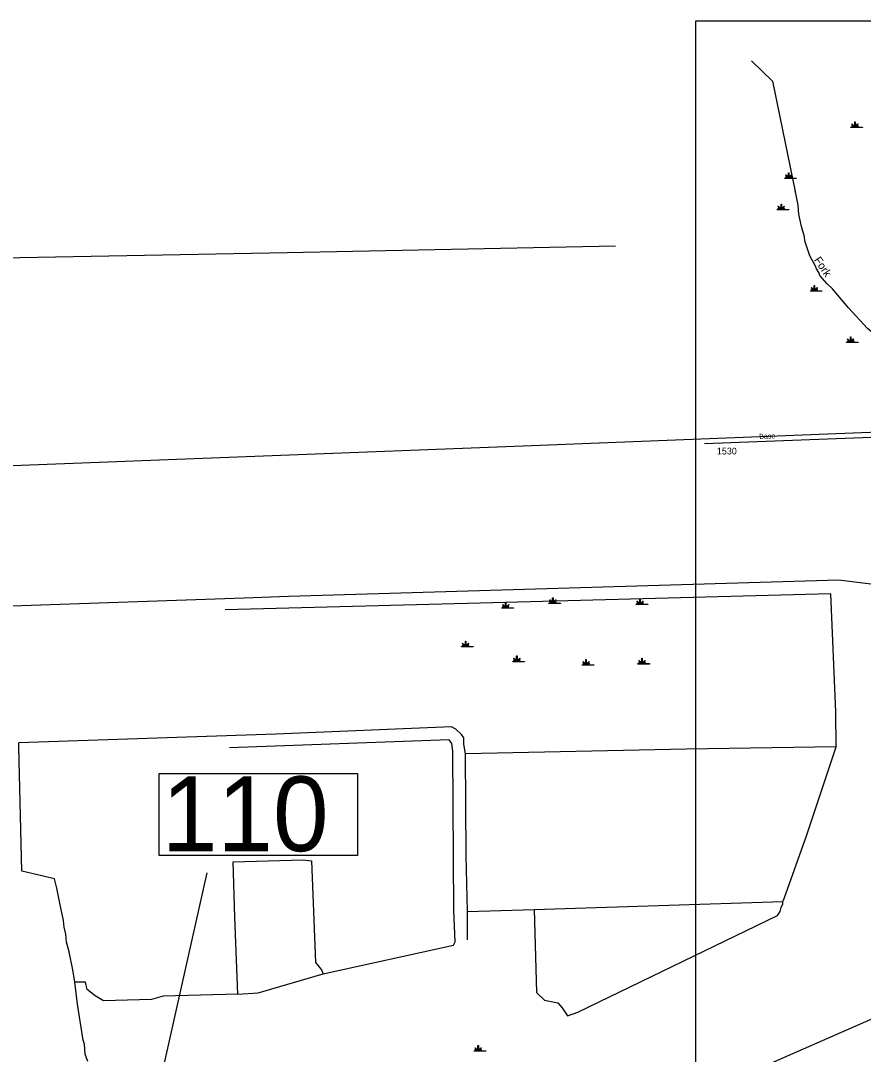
# Model space of a CAD drawing. Extents: x 2532689 to 2764727, y 536648 to 732970.
# Drawn here: x 2613131 to 2628920, y 672968 to 692342 of the extents above; entities that cross this region are included whole.
import ezdxf

# ---------------------------------------------------------------- set-up
doc = ezdxf.new("R2010")
doc.units = 0
for name, color, linetype in [('Exist Hydrographic Creek Single Shore', 7, 'Continuous'), ('Exist Hydrographic Creek Single Shore Label', 7, 'Continuous'), ('Exist Hydrographic Swamp CELL', 7, 'Continuous'), ('Exist Railroad Mainline', 7, 'Continuous'), ('Exist Road Secondary Structure Standard Bridge Number Label', 7, 'Continuous'), ('Exist Road Secondary Type 51 Attributed', 7, 'Continuous'), ('Exist Road Secondary Type 51 Label', 7, 'Continuous'), ('Exist Road Secondary Type 51 Number Label', 7, 'Continuous'), ('Map Preparation Inset Cut Line', 7, 'Continuous')]:
    doc.layers.add(name, color=color, linetype=linetype)

msp = doc.modelspace()

# ---------------------------------------------------------------- linework, layer by layer
at = {"layer": 'Exist Hydrographic Creek Single Shore'}
for p, q in [((2622750, 675683), (2627414, 675833)), ((2621501, 675643), (2622750, 675683)), ((2621503, 675117), (2621501, 675643))]:
    msp.add_line(p, q, dxfattribs=at)
for points in [[(2626823, 691587), (2627218, 691211), (2627643, 689138)], [(2630789, 684697), (2630782, 684989), (2630728, 685203), (2630606, 685451), (2630436, 685605), (2629635, 686065), (2629406, 686227), (2628999, 686575), (2628641, 686961), (2628342, 687313), (2628240, 687411), (2628103, 687566), (2628085, 687624), (2628042, 687688), (2628025, 687740), (2627921, 687936), (2627823, 688218), (2627821, 688293), (2627759, 688485), (2627713, 688716), (2627701, 688883), (2627653, 689100), (2627643, 689138)], [(2605512, 683752), (2605508, 684359), (2605536, 684987), (2605524, 685594), (2605794, 685815), (2608362, 687761), (2613118, 687901), (2618126, 687999), (2624275, 688120)], [(2612816, 684001), (2622544, 684373), (2630789, 684697)], [(2630615, 681410), (2630136, 681998), (2629755, 681907), (2629208, 681763), (2628464, 681854), (2618152, 681548), (2617319, 681521), (2612967, 681371)], [(2628412, 678730), (2628407, 679386), (2628311, 681602), (2621980, 681428), (2616966, 681300)], [(2621464, 678599), (2621435, 678782), (2621433, 678900), (2621390, 678964), (2621288, 679062), (2621204, 679104), (2617914, 678968), (2613095, 678804)], [(2618800, 674476), (2621239, 675012), (2621271, 675079), (2621250, 675662), (2621230, 678652), (2621210, 678796), (2621159, 678860), (2617044, 678716)], [(2614144, 674324), (2614106, 674555), (2614040, 674888), (2613987, 675069), (2613975, 675220), (2613947, 675353), (2613936, 675478), (2613863, 675800), (2613807, 676083), (2613762, 676255), (2613150, 676400), (2613099, 678729), (2613095, 678804)], [(2628412, 678730), (2625605, 678685), (2621464, 678599)], [(2627414, 675833), (2627438, 675890), (2627855, 677066), (2628412, 678730)], [(2621501, 675643), (2621479, 676692), (2621464, 678599)], [(2617199, 674093), (2617144, 675542), (2617114, 676575), (2618422, 676611), (2618580, 676592), (2618654, 674690), (2618765, 674550), (2618800, 674476)], [(2622750, 675683), (2622799, 674126), (2622944, 673981), (2623195, 673935), (2623280, 673837), (2623375, 673690), (2623573, 673760), (2627311, 675573), (2627360, 675647), (2627383, 675723), (2627415, 675790), (2627414, 675833)], [(2617199, 674093), (2617582, 674118), (2618800, 674476)], [(2617199, 674093), (2615800, 674056), (2615584, 673995), (2614685, 673968), (2614524, 674063), (2614380, 674186), (2614344, 674319), (2614144, 674324)], [(2614391, 672837), (2614339, 672969), (2614326, 673159), (2614300, 673233), (2614194, 673906), (2614144, 674324)]]:
    msp.add_lwpolyline(points, dxfattribs=at)
at = {"layer": 'Exist Hydrographic Swamp CELL'}
for points in [[(2628689, 690346), (2628741, 690346), (2628743, 690350), (2628705, 690364), (2628708, 690370), (2628746, 690354), (2628747, 690357), (2628703, 690401), (2628708, 690406), (2628753, 690361), (2628759, 690363), (2628759, 690446), (2628767, 690446), (2628767, 690363), (2628773, 690361), (2628818, 690406), (2628823, 690401), (2628779, 690357), (2628781, 690353), (2628822, 690372), (2628824, 690367), (2628783, 690349), (2628785, 690346), (2628906, 690346), (2628906, 690339), (2628689, 690339)], [(2627448, 689389), (2627500, 689390), (2627502, 689393), (2627464, 689408), (2627467, 689413), (2627505, 689397), (2627506, 689400), (2627462, 689445), (2627467, 689450), (2627512, 689405), (2627518, 689407), (2627518, 689490), (2627526, 689490), (2627526, 689407), (2627532, 689405), (2627577, 689450), (2627582, 689445), (2627538, 689400), (2627540, 689397), (2627581, 689415), (2627583, 689410), (2627542, 689392), (2627544, 689390), (2627665, 689389), (2627665, 689382), (2627448, 689382)], [(2627307, 688804), (2627360, 688804), (2627362, 688807), (2627323, 688822), (2627326, 688827), (2627364, 688812), (2627366, 688814), (2627321, 688859), (2627326, 688864), (2627372, 688819), (2627378, 688821), (2627378, 688904), (2627385, 688904), (2627385, 688821), (2627392, 688819), (2627437, 688864), (2627442, 688859), (2627398, 688814), (2627400, 688811), (2627440, 688829), (2627443, 688824), (2627402, 688807), (2627404, 688804), (2627525, 688804), (2627525, 688797), (2627307, 688797)], [(2627928, 687280), (2627980, 687281), (2627982, 687284), (2627944, 687299), (2627947, 687304), (2627985, 687288), (2627986, 687291), (2627942, 687336), (2627947, 687341), (2627992, 687296), (2627999, 687298), (2627999, 687381), (2628006, 687381), (2628006, 687298), (2628012, 687296), (2628057, 687341), (2628063, 687336), (2628018, 687291), (2628020, 687288), (2628061, 687306), (2628063, 687301), (2628022, 687283), (2628024, 687281), (2628145, 687280), (2628145, 687273), (2627928, 687273)], [(2628607, 686316), (2628659, 686316), (2628661, 686319), (2628623, 686334), (2628626, 686340), (2628664, 686324), (2628665, 686327), (2628621, 686371), (2628626, 686376), (2628671, 686331), (2628678, 686333), (2628678, 686416), (2628685, 686416), (2628685, 686333), (2628691, 686331), (2628736, 686376), (2628742, 686371), (2628697, 686327), (2628699, 686323), (2628740, 686342), (2628742, 686337), (2628701, 686319), (2628703, 686316), (2628824, 686316), (2628824, 686309), (2628607, 686309)], [(2622146, 681339), (2622198, 681339), (2622200, 681343), (2622162, 681358), (2622165, 681363), (2622203, 681347), (2622204, 681350), (2622160, 681394), (2622165, 681400), (2622210, 681354), (2622217, 681356), (2622217, 681440), (2622224, 681440), (2622224, 681356), (2622230, 681354), (2622275, 681400), (2622281, 681394), (2622236, 681350), (2622238, 681346), (2622279, 681365), (2622281, 681360), (2622240, 681342), (2622242, 681339), (2622363, 681339), (2622363, 681332), (2622146, 681332)], [(2623028, 681425), (2623080, 681425), (2623082, 681429), (2623044, 681444), (2623047, 681449), (2623085, 681433), (2623086, 681436), (2623042, 681481), (2623047, 681486), (2623092, 681440), (2623098, 681443), (2623098, 681526), (2623106, 681526), (2623106, 681443), (2623112, 681440), (2623157, 681486), (2623162, 681481), (2623118, 681436), (2623120, 681432), (2623161, 681451), (2623163, 681446), (2623122, 681428), (2623124, 681425), (2623245, 681425), (2623245, 681418), (2623028, 681418)], [(2624662, 681404), (2624715, 681404), (2624717, 681407), (2624679, 681422), (2624682, 681427), (2624719, 681412), (2624721, 681414), (2624677, 681459), (2624682, 681464), (2624727, 681419), (2624733, 681421), (2624733, 681504), (2624741, 681504), (2624741, 681421), (2624747, 681419), (2624792, 681464), (2624797, 681459), (2624753, 681414), (2624755, 681411), (2624796, 681429), (2624798, 681424), (2624757, 681407), (2624759, 681404), (2624880, 681404), (2624880, 681397), (2624662, 681397)], [(2621393, 680614), (2621445, 680614), (2621447, 680618), (2621409, 680633), (2621412, 680638), (2621450, 680622), (2621451, 680625), (2621407, 680670), (2621412, 680675), (2621457, 680629), (2621464, 680632), (2621464, 680715), (2621471, 680715), (2621471, 680632), (2621477, 680629), (2621522, 680675), (2621528, 680670), (2621483, 680625), (2621485, 680622), (2621526, 680640), (2621529, 680635), (2621488, 680617), (2621489, 680614), (2621610, 680614), (2621610, 680607), (2621393, 680607)], [(2622354, 680334), (2622406, 680335), (2622408, 680338), (2622370, 680353), (2622373, 680358), (2622411, 680342), (2622412, 680345), (2622368, 680390), (2622373, 680395), (2622418, 680349), (2622424, 680352), (2622424, 680435), (2622432, 680435), (2622432, 680352), (2622438, 680349), (2622483, 680395), (2622488, 680390), (2622444, 680345), (2622446, 680342), (2622487, 680360), (2622489, 680355), (2622448, 680337), (2622450, 680335), (2622571, 680334), (2622571, 680327), (2622354, 680327)], [(2623651, 680270), (2623704, 680270), (2623706, 680274), (2623668, 680288), (2623671, 680294), (2623708, 680278), (2623710, 680281), (2623666, 680325), (2623671, 680330), (2623716, 680285), (2623722, 680287), (2623722, 680370), (2623730, 680370), (2623730, 680287), (2623736, 680285), (2623781, 680330), (2623786, 680325), (2623742, 680281), (2623744, 680277), (2623785, 680296), (2623787, 680291), (2623746, 680273), (2623748, 680270), (2623869, 680270), (2623869, 680263), (2623651, 680263)], [(2624698, 680291), (2624751, 680291), (2624753, 680295), (2624715, 680310), (2624718, 680315), (2624755, 680299), (2624757, 680302), (2624713, 680347), (2624718, 680352), (2624763, 680306), (2624769, 680309), (2624769, 680392), (2624777, 680392), (2624776, 680309), (2624783, 680306), (2624828, 680352), (2624833, 680347), (2624789, 680302), (2624791, 680299), (2624832, 680317), (2624834, 680312), (2624793, 680294), (2624795, 680291), (2624916, 680291), (2624916, 680284), (2624698, 680284)], [(2621629, 673033), (2621681, 673033), (2621683, 673037), (2621645, 673051), (2621648, 673057), (2621686, 673041), (2621687, 673044), (2621643, 673088), (2621648, 673093), (2621693, 673048), (2621700, 673050), (2621700, 673133), (2621707, 673133), (2621707, 673050), (2621713, 673048), (2621758, 673093), (2621764, 673088), (2621719, 673044), (2621721, 673040), (2621762, 673059), (2621764, 673054), (2621724, 673036), (2621725, 673033), (2621846, 673033), (2621846, 673026), (2621629, 673026)]]:
    msp.add_lwpolyline(points, close=True, dxfattribs=at)
at = {"layer": 'Exist Railroad Mainline'}
msp.add_lwpolyline([(2634694, 683213), (2634010, 676533), (2634013, 676503), (2633964, 676274), (2633866, 676068), (2633813, 675949), (2633702, 675822), (2633667, 675772), (2633421, 675568), (2633372, 675529), (2633048, 675366), (2632689, 675214), (2631851, 674848), (2620186, 669728), (2620039, 669645), (2619779, 669458), (2619608, 669323), (2615924, 666577)], dxfattribs=at)
at = {"layer": 'Exist Road Secondary Structure Standard Bridge Number Label'}
msp.add_line((2615313, 670545), (2616626, 676370), dxfattribs=at)
msp.add_lwpolyline([(2615727, 678233), (2619443, 678233), (2619443, 676697), (2615727, 676697)], close=True, dxfattribs=at)
at = {"layer": 'Exist Road Secondary Type 51 Attributed'}
msp.add_lwpolyline([(2625942, 684415), (2629072, 684535), (2630845, 684638)], dxfattribs=at)
at = {"layer": 'Map Preparation Inset Cut Line'}
msp.add_lwpolyline([(2625780, 692342), (2701222, 692342), (2701222, 670513), (2663418, 670513), (2663418, 648997), (2625780, 648997)], close=True, dxfattribs=at)

# ---------------------------------------------------------------- texts
at = {"layer": 'Exist Hydrographic Creek Single Shore Label'}
msp.add_text('Fork', height=150, rotation=303.8381, dxfattribs=at).set_placement((2627989, 687856))
at = {"layer": 'Exist Road Secondary Structure Standard Bridge Number Label'}
msp.add_text('110', height=1400, dxfattribs=at).set_placement((2615777, 676776))
at = {"layer": 'Exist Road Secondary Type 51 Label'}
msp.add_text('Base ', height=95, rotation=2.1974, dxfattribs=at).set_placement((2626972, 684503))
at = {"layer": 'Exist Road Secondary Type 51 Number Label'}
msp.add_text('1530', height=125, dxfattribs=at).set_placement((2626177, 684212))

doc.saveas('drawing.dxf')
